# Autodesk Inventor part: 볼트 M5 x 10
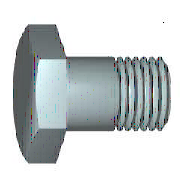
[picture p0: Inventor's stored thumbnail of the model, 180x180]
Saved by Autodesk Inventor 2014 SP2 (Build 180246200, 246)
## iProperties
IsCustomPart: 1
Created: 2012-02
Part Number: 볼트 M5 x 10
Material: 강철, 연강
Description: 6각 머리 볼트 및 6각 머리 나사
Document SubType Name: Modeling
Standard: KS B 1002
Designer: mduedu
Standards Organization: KS
Language: ko-KR
Size Designation: C  M 5 x 10
Categories: <MemberInstance><Categories><Category DisplayName="조임쇠" InternalName="e4da775c-781d-43d5-af7c-5136215cf5a6" Mnemonic="FSTN"><Category DisplayName="볼트" InternalN
Density: 1 g/cm^3
Appearance: 강철
Author: mduedu
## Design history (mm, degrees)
sketch "스케치1"
  geometry: L1 (0, 2.5)-(10, 2.5); L2 (10, 2.5)-(10, 0); L3 (10, 0)-(0, 0); L4 (-2, 0)-(12, 0) reference; L5 (0, -0.5)-(0, 3) reference; L6 (0, 2.5)-(0, 0)
  constraints: 8 end point, 3 point on line, 1 collinear
  dimensions: "d2" = 5 diameter of L1 L3 (= GD); "d59" = 10 distance between parallel lines of L2 L5 (= NLG)
revolve "본체" sketch "스케치1" stored, may be unused: angle "d12" = 90 deg
sketch "스케치2"
  geometry: L1 (0, 4.619)-(4, 2.309); L2 (4, 2.309)-(4, -2.309); L3 (4, -2.309)-(0, -4.619); L4 (0, -4.619)-(-4, -2.309); L5 (-4, -2.309)-(-4, 2.309); L6 (-4, 2.309)-(0, 4.619); L7 (-5.6, 0)-(5.6, 0) reference; L8 (0, 6.466)-(0, -6.466) reference; 2 further points
  constraints: 12 end point, 2 midpoint, 1 coincident, 1 vertical, 11 other
  dimensions: "d11" = 8 distance between parallel lines of L5 L2 (= SW)
extrude "머리" join sketch "스케치2" distance "d3" = 3.5 (= KOH); taper "d4" = 0 deg
revolve "모따기1" stored, may be unused: angle "d21" = 90 deg
workplane "Work Plane1"
body "Solid1"
feature "스레드" dims "d15" = 7.6 (= GEL), "d16" = 0
chamfer "모따기2" distance "d6" = 0.49076 (= -0.5 x SPD + 0.5 x GD); stored, may be unused: second distance "d7" = 0.49086 (computed from GUL), angle "d55" = 45 deg
sketch "스케치4"
  geometry: L1 (-3.038, 4.8)-(-3.5, 4); L2 (-1.1, 0)-(-0.234, 0); L3 (-4.153, 0)-(0.419, 0) reference; L4 (-3.5, 4.8)-(-3.038, 4.8); L5 (-3.5, 4)-(-3.5, 4.8); L6 (0, 5.76)-(0, -0.96) reference
  constraints: 8 end point, 1 parallel, 1 perpendicular, 1 point on line
  dimensions: "d65" = 8 diameter of L1.end L2 (= SW); "d67" = 30 deg angle of L1 L5 (= ANG1); "d68" = 9.6 diameter of L4 L2 (= 1.2 x SW); "d69" = 3.5 distance between parallel lines of L5 L6 (= KOH)
other parameters: "NLG" = 10 [user parameter; used in 1 equation term], "GD" = 5 (= NND) [user parameter; used in 2 equation terms], "BDM" = 5 (= NND) [user parameter], "KOH" = 3.5 [user parameter; used in 2 equation terms], "GEL" = 7.6 [user parameter; used in 1 equation term], "SW" = 8 [user parameter; used in 5 equation terms], "SW0" = 8 (= SW) [user parameter], "SPD" = 4.01848 (= NND - 1.2269 x PTC) [user parameter; used in 1 equation term], "SD2" = 5 (= NND) [user parameter], "SD" = 0 [user parameter], "ANG1" = 30 deg [user parameter; used in 1 equation term], "GAL" = 0.49076 (= 0.61345 x PTC) [user parameter], "GUL" = 0.49076 (= 0.61345 x PTC) [user parameter; used in 1 equation term], "d8" = 0, "RR" = 0.2 [user parameter], "d58" = 0, "RR1" = 0.1 [user parameter], "TPU" = 12.5 (computed from PTC) [user parameter], "GD1" = 4.01848 (= THREADDIA - 1.2269 x PTC) [user parameter], "THREADDIA" = 5 [user parameter; used in 1 equation term], "TOA" = 30 deg [user parameter], "PTC" = 0.8 [user parameter; used in 5 equation terms], "NND" = 5 [user parameter; used in 4 equation terms], "E0" = 9.24 (= 1.155 x SW) [user parameter]
